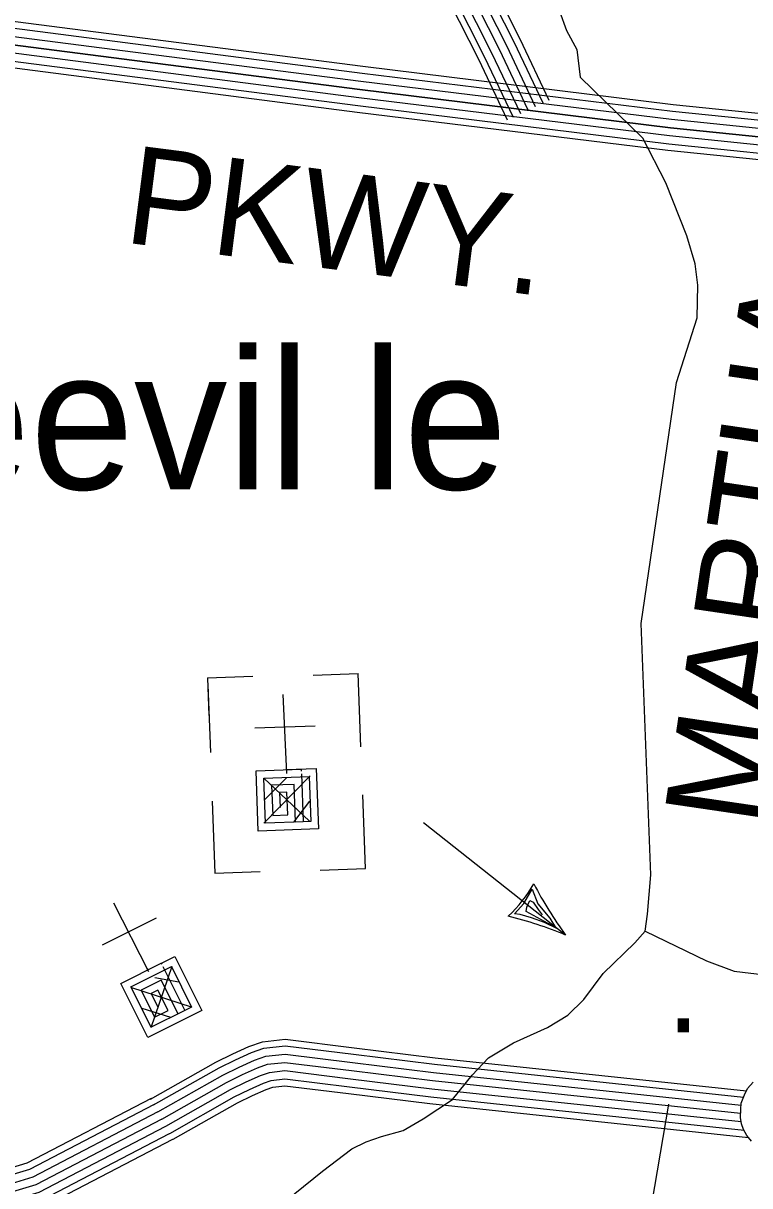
# Model space of a CAD drawing. Extents: x 1788175 to 1969470, y 584502 to 738744.
# Drawn here: x 1842257 to 1845006, y 676844 to 681239 of the extents above; entities that cross this region are included whole.
import ezdxf

# ---------------------------------------------------------------- set-up
doc = ezdxf.new("R2010")
doc.units = 0
for name, color, linetype in [('DESIGN - ROW - Right-of-Way and Easement Labels', 7, 'Continuous'), ('DESIGN - TRANSPORTATION - Text', 7, 'Continuous'), ('DESIGN - UTILITIES - Cable (Overhead) with Text', 7, 'Continuous'), ('DESIGN - UTILITIES - Cable (Underground) with Text', 7, 'Continuous'), ('SURVEY - TRANSPORTATION - Roads', 7, 'Continuous'), ('SURVEY - VEGETATION - Features with Text', 7, 'Continuous')]:
    doc.layers.add(name, color=color, linetype=linetype)

msp = doc.modelspace()

# ---------------------------------------------------------------- linework, layer by layer
at = {"layer": 'DESIGN - TRANSPORTATION - Text'}
for points in [[(1843433, 681737), (1843459.2, 681678), (1843485.4, 681651.7), (1843524.8, 681632.1), (1843590.4, 681618.9), (1843656, 681599.3), (1843734.7, 681586.1), (1843813.4, 681579.6), (1843879, 681573), (1843951.1, 681546.8), (1844010.1, 681527.1), (1844056.1, 681507.4), (1844134.8, 681448.4), (1844193.8, 681409.1), (1844226.6, 681363.1), (1844285.6, 681284.4), (1844311.9, 681212.3), (1844351.2, 681140.1), (1844364.3, 681035.2), (1844601.7, 680804.7)], [(1844809.7, 680249.4), (1844799.7, 680329.8), (1844767.9, 680435.8), (1844688.6, 680635.4), (1844601.7, 680804.7)], [(1843180.4, 676730.3), (1843388.9, 676899.1), (1843500.1, 676983.4), (1843554.4, 677010.5), (1843612.6, 677029.6), (1843694.9, 677052.3), (1843769.5, 677097.2), (1843880.5, 677169.5), (1843955.9, 677262.3), (1844016.9, 677327.4), (1844111.6, 677384), (1844240.4, 677441.9), (1844317.1, 677488.8), (1844377.9, 677547.8), (1844451.4, 677646.8), (1844571.1, 677762.9), (1844609.7, 677806.4), (1844618.7, 677870.3), (1844630.8, 678019.1), (1844594.4, 678969.6), (1844729.1, 679881), (1844806.8, 680124.8), (1844809.7, 680249.4)], [(1844609.7, 677806.4), (1844841.7, 677694.6), (1844946.9, 677654.9), (1845062.5, 677641), (1845166.1, 677625.3), (1845269.6, 677601.7), (1845341.2, 677578.5), (1845404.5, 677571.5)]]:
    msp.add_lwpolyline(points, dxfattribs=at)
at = {"layer": 'DESIGN - UTILITIES - Cable (Overhead) with Text'}
for p, q in [((1844308.9, 677791.9), (1843771.6, 678215.5)), ((1844151.5, 677910.7), (1844182.7, 677965.6)), ((1844182.7, 677965.6), (1844204.5, 677909.4)), ((1844116.1, 677872.6), (1844151.5, 677910.7)), ((1844162.8, 677897.7), (1844173.4, 677923.1)), ((1844173.4, 677923.1), (1844186.4, 677915.6)), ((1844186.4, 677915.6), (1844205.4, 677888.4)), ((1844204.5, 677909.4), (1844249.4, 677855.1)), ((1844136.7, 677869.7), (1844116.1, 677872.6)), ((1844179.6, 677857.5), (1844136.7, 677869.7)), ((1844160.3, 677880.8), (1844162.8, 677897.7)), ((1844270.7, 677820.7), (1844160.3, 677880.8)), ((1844205.4, 677888.4), (1844220.7, 677868.4)), ((1844228.6, 677839.2), (1844179.6, 677857.5)), ((1844281.4, 677813.7), (1844228.6, 677839.2)), ((1844249.4, 677855.1), (1844270.7, 677820.7))]:
    msp.add_line(p, q, dxfattribs=at)
for centre, radius, start, end in [((1843727.1, 678250.6), 532.3, 313.3167, 330.1751), ((1845423.9, 678615.8), 1386.4, 207.0252, 216.4637), ((1843715.7, 676357.4), 1552.3, 67.5335, 75.9612)]:
    msp.add_arc(centre, radius, start, end, dxfattribs=at)
at = {"layer": 'DESIGN - UTILITIES - Cable (Underground) with Text'}
for p, q in [((1842954.6, 678764.1), (1843125.6, 678770.4)), ((1842954.6, 678764.1), (1842959.9, 678621.7)), ((1843353.7, 678774.6), (1843524.6, 678781)), ((1843534.9, 678503.7), (1843524.6, 678781)), ((1842955.6, 678738.5), (1842965.1, 678482.4)), ((1843361.9, 678582), (1843133.9, 678573.6)), ((1843552, 678043.1), (1843541.7, 678321.9)), ((1842971.9, 678297.9), (1842982, 678026.2)), ((1843381, 678036.7), (1843552, 678043.1)), ((1842982, 678026.2), (1843152.9, 678032.5)), ((1842760.4, 677855.5), (1842556.4, 677753.5))]:
    msp.add_line(p, q, dxfattribs=at)
for points in [[(1843238.9, 678701.5), (1843252.5, 678402.4)], [(1843251.6, 678421.4), (1843251.8, 678417.2), (1843365.8, 678421.4), (1843374.2, 678193.4), (1843146.3, 678185), (1843137.9, 678412.9), (1843308.8, 678419.3), (1843309.1, 678411.4)], [(1843342.6, 678394), (1843167.2, 678214.7)], [(1843309.5, 678401.5), (1843316.2, 678219.8), (1843173.7, 678214.5), (1843167.4, 678385.5), (1843338.4, 678391.8), (1843344.7, 678220.9), (1843287.7, 678218.8), (1843282.4, 678361.2), (1843197, 678358.1), (1843201.2, 678244.1), (1843258.2, 678246.2), (1843255, 678331.7), (1843226.5, 678330.6), (1843228.6, 678273.6)], [(1843167, 678384.4), (1843339.7, 678222.6)], [(1843254.9, 678387.7), (1843171.6, 678304.4)], [(1843340, 678298.3), (1843279.6, 678218.9)], [(1842599.1, 677913.3), (1842731.2, 677654.6)], [(1842726.2, 677664.3), (1842728.5, 677659.8), (1842830.5, 677710.8), (1842932.5, 677506.8), (1842728.5, 677404.8), (1842626.5, 677608.8), (1842779.5, 677685.3), (1842781.3, 677681.7)], [(1842785.9, 677672.6), (1842868.8, 677506.8), (1842741.2, 677443.1), (1842664.7, 677596), (1842817.8, 677672.6), (1842894.3, 677519.5), (1842843.3, 677494.1), (1842779.5, 677621.6), (1842703, 677583.3), (1842754, 677481.3), (1842805, 677506.8), (1842766.8, 677583.3), (1842741.2, 677570.6), (1842766.8, 677519.5)], [(1842819.3, 677673.4), (1842739.8, 677441.3)], [(1842755.4, 677631.7), (1842845.4, 677614.7)], [(1842666.8, 677593.8), (1842892.3, 677520.9)], [(1842705.9, 677515.6), (1842814.1, 677481.7)]]:
    msp.add_lwpolyline(points, dxfattribs=at)
at = {"layer": 'SURVEY - TRANSPORTATION - Roads'}
for points in [[(1844246.8, 680947.7), (1844137.1, 681178.6), (1843846.7, 681752.4), (1843754.5, 681949.6), (1843711.3, 681999.1), (1843670.8, 682040.8), (1843614.1, 682076.5), (1843508.5, 682101.9), (1842138.8, 682301.2), (1840817, 682504.2), (1840751.3, 682505), (1840674.7, 682481.8), (1840611.1, 682404.1), (1840586.9, 682273.6), (1840522.4, 681458.4), (1840519.6, 681415.3), (1840523.4, 681313.6), (1840628.6, 681271.9), (1841940.1, 681104.6)], [(1844223.6, 680936.6), (1844114, 681167.3), (1843823.6, 681741.2), (1843732.7, 681935.4), (1843692.4, 681981.7), (1843654.5, 682020.7), (1843603.9, 682052.5), (1843503.6, 682076.6), (1842135, 682275.7), (1840814.8, 682478.5), (1840755, 682479.2), (1840689.7, 682459.4), (1840635.2, 682392.9), (1840612.4, 682270.2), (1840548.1, 681456.6), (1840545.3, 681415), (1840548.5, 681331.3), (1840635.1, 681297), (1841943.4, 681130.1)], [(1844195.5, 680923.3), (1844086.2, 681153.6), (1843795.7, 681727.6), (1843706.5, 681918.3), (1843669.6, 681960.7), (1843634.9, 681996.4), (1843591.7, 682023.5), (1843497.8, 682046.1), (1842130.4, 682245.1), (1840812.3, 682447.5), (1840759.4, 682448.2), (1840707.7, 682432.5), (1840664.2, 682379.4), (1840643.2, 682266.1), (1840579, 681454.4), (1840576.4, 681414.5), (1840578.7, 681352.7), (1840642.9, 681327.3), (1841947.3, 681160.9)], [(1844167.5, 680910), (1844058.4, 681140), (1843767.8, 681714), (1843680.3, 681901.3), (1843646.8, 681939.7), (1843615.2, 681972.1), (1843579.5, 681994.6), (1843491.9, 682015.6), (1842125.8, 682214.4), (1840809.7, 682416.6), (1840763.8, 682417.1), (1840725.7, 682405.6), (1840693.2, 682365.9), (1840673.9, 682262.1), (1840609.9, 681452.1), (1840607.4, 681414.1), (1840608.9, 681374.1), (1840650.7, 681357.5), (1841951.2, 681191.6)], [(1844167.5, 680910), (1844058.4, 681140), (1843767.8, 681714), (1843680.3, 681901.3), (1843646.8, 681939.7), (1843615.2, 681972.1), (1843579.5, 681994.6), (1843491.9, 682015.6), (1842125.8, 682214.4), (1840809.7, 682416.6), (1840763.8, 682417.1), (1840725.7, 682405.6), (1840693.2, 682365.9), (1840673.9, 682262.1), (1840609.9, 681452.1), (1840607.4, 681414.1), (1840608.9, 681374.1), (1840650.7, 681357.5), (1841951.2, 681191.6)], [(1844139.5, 680896.7), (1844030.5, 681126.3), (1843740, 681700.5), (1843654, 681884.2), (1843624, 681918.7), (1843595.6, 681947.8), (1843567.3, 681965.6), (1843486, 681985.2), (1842121.2, 682183.7), (1840807.2, 682385.6), (1840768.2, 682386.1), (1840743.7, 682378.6), (1840722.2, 682352.4), (1840704.7, 682258), (1840640.8, 681449.9), (1840638.5, 681413.7), (1840639.1, 681395.4), (1840658.5, 681387.8), (1841955.1, 681222.4)], [(1844111.5, 680883.4), (1844002.7, 681112.7), (1843712.1, 681686.9), (1843627.8, 681867.1), (1843601.2, 681897.7), (1843576, 681923.6), (1843555.1, 681936.7), (1843480.2, 681954.7), (1842116.7, 682153.1), (1840804.6, 682354.6), (1840772.6, 682355), (1840761.7, 682351.7), (1840751.3, 682339), (1840735.5, 682253.9), (1840671.7, 681447.7), (1840669.5, 681413.3), (1840669.4, 681416.8), (1840666.2, 681418.1), (1841959.1, 681253.1)], [(1844089.2, 680872.8), (1843980.5, 681101.8), (1843689.9, 681676.1), (1843606.9, 681853.5), (1843583, 681880.9), (1843560.3, 681904.2), (1843545.4, 681913.6), (1843475.5, 681930.4), (1842113, 682128.6), (1840802.6, 682329.9), (1840776.1, 682330.2), (1840776.1, 682330.2), (1840774.4, 682328.2), (1840760, 682250.7), (1840696.4, 681445.9), (1840694.2, 681412.9), (1840693.5, 681433.9), (1840672.5, 681442.2), (1841962.2, 681277.6)], [(1845258.1, 680849.7), (1844712.9, 680905.5), (1843538.8, 681049.8), (1841959.1, 681253.1)], [(1845246.5, 680876.7), (1844715.8, 680931), (1843542, 681075.3), (1841962.4, 681278.6)], [(1845272.2, 680817.1), (1844709.4, 680874.7), (1843534.9, 681019), (1841955.2, 681222.4)], [(1845286.2, 680784.5), (1844706, 680843.9), (1843531, 680988.3), (1841951.2, 681191.6)], [(1841951.2, 681191.6), (1843531, 680988.3), (1844706, 680843.9), (1845286.2, 680784.5)], [(1845314.2, 680719.3), (1844699, 680782.2), (1843523.3, 680926.7), (1841943.3, 681130.1)], [(1845300.2, 680751.9), (1844702.5, 680813.1), (1843527.2, 680957.5), (1841947.3, 681160.9)], [(1845325.4, 680693.3), (1844696.3, 680757.7), (1843520.2, 680902.2), (1841940.1, 681105.6)], [(1842752.5, 677150.9), (1842281.1, 676905.2), (1842205.5, 676882.5), (1842120.9, 676876.5), (1841777.8, 676857.1), (1841519.9, 676876.4), (1840837.5, 676935.5), (1840541.1, 676955.2), (1840248.3, 676968.2), (1839929.4, 677013.8), (1839150.4, 677112), (1838885.6, 677163.7), (1838667.8, 677221.3), (1838273.2, 677373.4), (1836903.4, 678144.5)], [(1842740.6, 677173.7), (1842271.4, 676929.1), (1842200.8, 676908), (1842119.2, 676902.2), (1841778, 676882.8), (1841522, 676902), (1840839.5, 676961.1), (1840542.5, 676980.9), (1840250.7, 676993.9), (1839932.8, 677039.3), (1839154.5, 677137.4), (1838891.3, 677188.7), (1838675.8, 677245.8), (1838284.2, 677396.7), (1836916, 678166.9)], [(1842781.2, 677095.9), (1842304.6, 676847.5), (1842216.7, 676821.2), (1842124.9, 676814.6), (1841777.2, 676794.9), (1841514.9, 676814.6), (1840832.8, 676873.6), (1840537.6, 676893.3), (1840242.5, 676906.4), (1839921.1, 676952.3), (1839140.6, 677050.7), (1838871.7, 677103.2), (1838648.7, 677162.2), (1838246.7, 677317.1), (1836873, 678090.5)], [(1842781.2, 677095.9), (1842304.6, 676847.5), (1842216.7, 676821.2), (1842124.9, 676814.6), (1841777.2, 676794.9), (1841514.9, 676814.6), (1840832.8, 676873.6), (1840537.6, 676893.3), (1840242.5, 676906.4), (1839921.1, 676952.3), (1839140.6, 677050.7), (1838871.7, 677103.2), (1838648.7, 677162.2), (1838246.7, 677317.1), (1836873, 678090.5)], [(1842766.8, 677123.4), (1842292.9, 676876.3), (1842211.1, 676851.8), (1842122.9, 676845.6), (1841777.5, 676826), (1841517.4, 676845.5), (1840835.1, 676904.5), (1840539.3, 676924.3), (1840245.4, 676937.3), (1839925.2, 676983.1), (1839145.5, 677081.4), (1838878.6, 677133.4), (1838658.3, 677191.8), (1838260, 677345.2), (1836888.2, 678117.5)], [(1842795.5, 677068.4), (1842316.3, 676818.6), (1842222.3, 676790.5), (1842126.8, 676783.7), (1841777, 676763.9), (1841512.4, 676783.7), (1840830.4, 676842.7), (1840535.9, 676862.4), (1840239.6, 676875.5), (1839917, 676921.6), (1839135.7, 677020.1), (1838864.8, 677073), (1838639.1, 677132.7), (1838233.5, 677289), (1836857.8, 678063.5)], [(1842821.3, 677019), (1842337.3, 676766.7), (1842232.4, 676735.4), (1842130.4, 676728.1), (1841776.4, 676708), (1841507.9, 676728.2), (1840826.1, 676787.2), (1840532.8, 676806.7), (1840234.4, 676820), (1839909.5, 676866.4), (1839126.9, 676965.1), (1838852.3, 677018.6), (1838621.9, 677079.6), (1838209.7, 677238.5), (1836830.5, 678014.9)], [(1842809.8, 677040.9), (1842328, 676789.8), (1842227.9, 676759.8), (1842128.8, 676752.7), (1841776.7, 676732.8), (1841509.9, 676752.8), (1840828, 676811.8), (1840534.2, 676831.4), (1840236.7, 676844.6), (1839912.8, 676890.9), (1839130.8, 676989.5), (1838857.8, 677042.7), (1838629.6, 677103.2), (1838220.2, 677260.9), (1836842.6, 678036.5)], [(1842738.4, 677171.3), (1842986.3, 677311.8), (1843050.2, 677342.9), (1843110.8, 677370.2), (1843161.9, 677388.3), (1843248, 677397.7), (1843509.3, 677365.4), (1843815.8, 677327.7), (1844993.2, 677202.7)], [(1842750.6, 677149.8), (1842997.8, 677289.9), (1843060.7, 677320.5), (1843120.1, 677347.2), (1843167.4, 677364.1), (1843247.8, 677372.8), (1843506.3, 677340.9), (1843813, 677303.2), (1844982.5, 677179)], [(1842765.9, 677122.9), (1843012.2, 677262.5), (1843073.8, 677292.4), (1843131.6, 677318.5), (1843174.4, 677333.6), (1843247.6, 677341.6), (1843502.5, 677310.1), (1843809.4, 677272.4), (1844972.8, 677148.8)], [(1842781.2, 677095.9), (1843026.6, 677235), (1843087, 677264.3), (1843143.2, 677289.7), (1843181.3, 677303.2), (1843247.4, 677310.4), (1843498.7, 677279.3), (1843805.9, 677241.6), (1844970.9, 677117.9)], [(1842781.2, 677095.9), (1843026.6, 677235), (1843087, 677264.3), (1843143.2, 677289.7), (1843181.3, 677303.2), (1843247.4, 677310.4), (1843498.7, 677279.3), (1843805.9, 677241.6), (1844970.9, 677117.9)], [(1842796.5, 677068.9), (1843041.1, 677207.6), (1843100.1, 677236.3), (1843154.8, 677260.9), (1843188.3, 677272.8), (1843247.1, 677279.2), (1843494.9, 677248.6), (1843802.4, 677210.8), (1844973, 677086.5)], [(1842811.7, 677042), (1843055.5, 677180.1), (1843113.2, 677208.2), (1843166.4, 677232.1), (1843195.3, 677242.4), (1843246.9, 677248), (1843491.1, 677217.8), (1843798.9, 677180), (1844984, 677054.1)], [(1842824.4, 677019.6), (1843067.5, 677157.4), (1843124.1, 677184.9), (1843176, 677208.2), (1843201, 677217.1), (1843246.7, 677222.1), (1843488, 677192.3), (1843795.9, 677154.4), (1845001.1, 677026.4)], [(1844698.7, 677152.6), (1844623.2, 676714.9), (1844626.5, 676664.8), (1844642.3, 676644.6), (1844682.1, 676636.1), (1845043.2, 676598)]]:
    msp.add_lwpolyline(points, dxfattribs=at)
at = {"layer": 'SURVEY - VEGETATION - Features with Text'}
msp.add_lwpolyline([(1845011.6, 677013.2), (1844994.7, 677034.5), (1844982.5, 677056.8), (1844974.5, 677077.6), (1844970.4, 677101.5), (1844971.5, 677133.9), (1844973.5, 677156.3), (1844985.8, 677187.3), (1844997.2, 677211.1), (1845018.7, 677235.9)], dxfattribs=at)

# ---------------------------------------------------------------- texts
at = {"layer": 'DESIGN - ROW - Right-of-Way and Easement Labels'}
for s, rotation, p in [('PKWY.', 352.665, (1842632.2, 680411.3)), ('MARTHA', 81.6295, (1845047.5, 678195.8))]:
    msp.add_text(s, height=370, rotation=rotation, dxfattribs=at).set_placement(p)
at = {"layer": 'DESIGN - UTILITIES - Cable (Underground) with Text'}
msp.add_text('.', height=343, dxfattribs=at).set_placement((1844690.6, 677423.6))
at = {"layer": 'SURVEY - VEGETATION - Features with Text'}
msp.add_text('Leevil le', height=528, dxfattribs=at).set_placement((1841498.1, 679476.8))

doc.saveas('drawing.dxf')
